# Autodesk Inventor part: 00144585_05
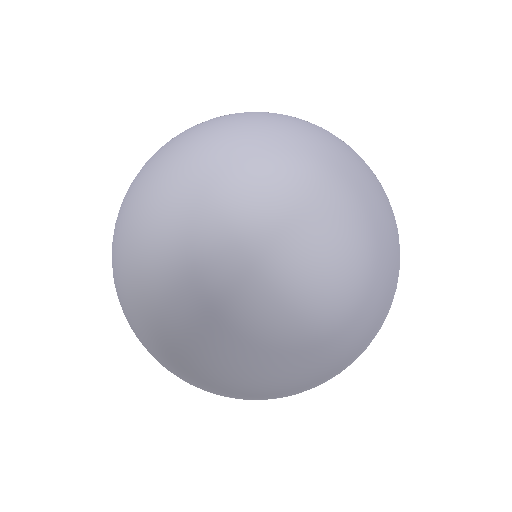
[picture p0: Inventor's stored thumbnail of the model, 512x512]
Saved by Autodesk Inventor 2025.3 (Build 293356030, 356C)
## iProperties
Created: 2021-02
Part Number: 00144585_05
Material: Generico
Document SubType Name: Modeling
Designer: R5800u
Density: 1 g/cm^3
Appearance: Default
Author: TraceParts
Sending System: SolidWorks 2021
Last Author: Albert
Last Saved: 2021-07-28
IsFastener: 1
TYPE: CATASM
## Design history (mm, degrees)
feature "Imported1"
node "Solido1"
